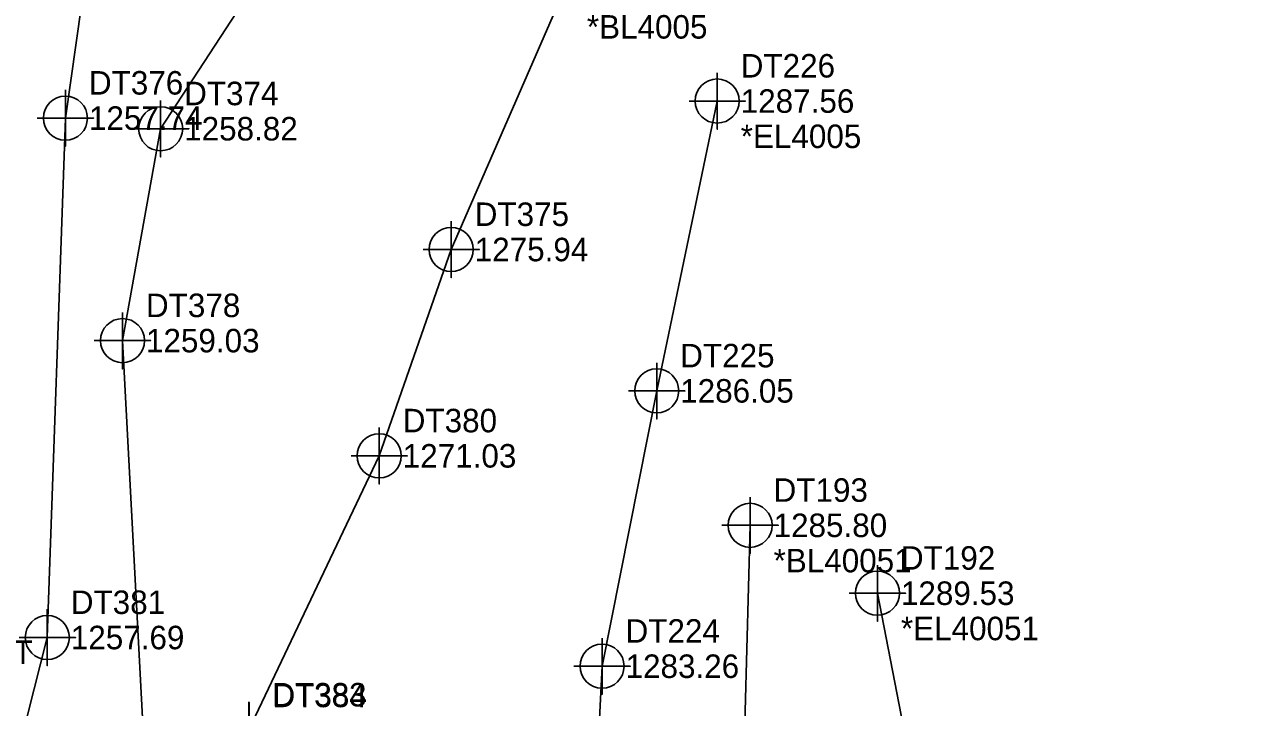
# Model space of a CAD drawing. Extents: x 1391270 to 1392151, y 960049 to 960667.
# Drawn here: x 1391612.7 to 1391741.8, y 960372.1 to 960444.8 of the extents above; entities that cross this region are included whole.
import ezdxf

# ---------------------------------------------------------------- set-up
doc = ezdxf.new("R2010")
doc.units = 0
for name, color, linetype in [('Exist DTM Breakline', 7, 'Continuous'), ('Exist DTM Breakline Cogo Comment', 7, 'Continuous'), ('Exist DTM Breakline Cogo Elevation', 7, 'Continuous'), ('Exist DTM Breakline Cogo Number', 7, 'Continuous'), ('Exist DTM Breakline Cogo Point CELL', 7, 'Continuous'), ('Exist DTM Breakline Underwater', 7, 'Continuous'), ('Exist DTM Breakline Underwater Cogo Elevation', 7, 'Continuous'), ('Exist DTM Breakline Underwater Cogo Number', 7, 'Continuous'), ('Exist DTM Breakline Underwater Cogo Point CELL', 7, 'Continuous'), ('Exist Hydro Stream or Body of Water', 7, 'Continuous'), ('Exist Hydro Stream or Body of Water Cogo Elevation', 7, 'Continuous'), ('Exist Hydro Stream or Body of Water Cogo Number', 7, 'Continuous'), ('Exist Hydro Stream or Body of Water Cogo Point CELL', 7, 'Continuous'), ('Exist Utilities Sanitary Sewer Manhole Cogo Comment', 7, 'Continuous')]:
    doc.layers.add(name, color=color, linetype=linetype)

msp = doc.modelspace()

# ---------------------------------------------------------------- linework, layer by layer
at = {"layer": 'Exist DTM Breakline'}
for p, q in [((1391670.034, 960448.283), (1391658.104, 960420.856)), ((1391658.104, 960420.856), (1391650.447, 960398.915)), ((1391650.447, 960398.915), (1391636.562, 960369.763))]:
    msp.add_line(p, q, dxfattribs=at)
for points in [[(1391677.683, 960326.497), (1391672.764, 960349.215), (1391674.149, 960376.543), (1391679.962, 960405.823), (1391686.399, 960436.645)], [(1391689.894, 960391.525), (1391689.18, 960365.157), (1391690.906, 960335.168), (1391693.62, 960320.244), (1391696.803, 960298.575), (1391694.311, 960295.44), (1391699.762, 960289.791)], [(1391945.147, 960195.757), (1391918.09, 960213.421), (1391881.206, 960222.292), (1391849.896, 960235.631), (1391826.517, 960251.571), (1391802.004, 960268.368), (1391783.721, 960280.05), (1391763.211, 960305.363), (1391726.912, 960330.123), (1391710.789, 960346.476), (1391703.438, 960384.306)]]:
    msp.add_lwpolyline(points, dxfattribs=at)
at = {"layer": 'Exist DTM Breakline Cogo Point CELL'}
for points in [[(1391686.399, 960439.645), (1391686.399, 960433.645), (1391686.399, 960436.645), (1391689.399, 960436.645), (1391683.399, 960436.645)], [(1391658.104, 960423.856), (1391658.104, 960417.856), (1391658.104, 960420.856), (1391661.104, 960420.856), (1391655.104, 960420.856)], [(1391679.962, 960408.823), (1391679.962, 960402.823), (1391679.962, 960405.823), (1391682.962, 960405.823), (1391676.962, 960405.823)], [(1391650.447, 960401.915), (1391650.447, 960395.915), (1391650.447, 960398.915), (1391653.447, 960398.915), (1391647.447, 960398.915)], [(1391689.894, 960394.525), (1391689.894, 960388.525), (1391689.894, 960391.525), (1391692.894, 960391.525), (1391686.894, 960391.525)], [(1391703.438, 960387.306), (1391703.438, 960381.306), (1391703.438, 960384.306), (1391706.438, 960384.306), (1391700.438, 960384.306)], [(1391674.149, 960379.543), (1391674.149, 960373.543), (1391674.149, 960376.543), (1391677.149, 960376.543), (1391671.149, 960376.543)], [(1391636.562, 960372.763), (1391636.562, 960366.763), (1391636.562, 960369.763), (1391639.562, 960369.763), (1391633.562, 960369.763)], [(1391636.599, 960372.686), (1391636.599, 960366.686), (1391636.599, 960369.686), (1391639.599, 960369.686), (1391633.599, 960369.686)]]:
    msp.add_lwpolyline(points, dxfattribs=at)
for centre in [(1391686.399, 960436.645), (1391658.104, 960420.856), (1391679.962, 960405.823), (1391650.447, 960398.915), (1391689.894, 960391.525), (1391703.438, 960384.306), (1391674.149, 960376.543)]:
    msp.add_circle(centre, 2.344, dxfattribs=at)
at = {"layer": 'Exist DTM Breakline Underwater'}
msp.add_lwpolyline([(1391637.721, 960501.208), (1391621.569, 960466.64), (1391617.066, 960434.832), (1391615.14, 960379.594), (1391599.785, 960319.127), (1391597.418, 960292.355)], dxfattribs=at)
at = {"layer": 'Exist DTM Breakline Underwater Cogo Point CELL'}
for points in [[(1391617.066, 960437.832), (1391617.066, 960431.832), (1391617.066, 960434.832), (1391620.066, 960434.832), (1391614.066, 960434.832)], [(1391615.14, 960382.594), (1391615.14, 960376.594), (1391615.14, 960379.594), (1391618.14, 960379.594), (1391612.14, 960379.594)]]:
    msp.add_lwpolyline(points, dxfattribs=at)
for centre in [(1391617.066, 960434.832), (1391615.14, 960379.594)]:
    msp.add_circle(centre, 2.344, dxfattribs=at)
at = {"layer": 'Exist Hydro Stream or Body of Water'}
msp.add_lwpolyline([(1391649.062, 960494.038), (1391648.634, 960466.546), (1391627.196, 960433.7), (1391623.135, 960411.167), (1391625.85, 960360.364), (1391618.453, 960319.772), (1391609.949, 960287.686), (1391599.63, 960231.778)], dxfattribs=at)
at = {"layer": 'Exist Hydro Stream or Body of Water Cogo Point CELL'}
for points in [[(1391624.196, 960433.7), (1391630.196, 960433.7), (1391627.196, 960433.7), (1391627.196, 960430.7), (1391627.196, 960436.7)], [(1391620.135, 960411.167), (1391626.135, 960411.167), (1391623.135, 960411.167), (1391623.135, 960408.167), (1391623.135, 960414.167)]]:
    msp.add_lwpolyline(points, dxfattribs=at)
for centre in [(1391627.196, 960433.7), (1391623.135, 960411.167)]:
    msp.add_circle(centre, 2.344, dxfattribs=at)

# ---------------------------------------------------------------- texts
at = {"layer": 'Exist DTM Breakline Cogo Comment'}
for s, p in [('*BL4005', (1391672.534, 960443.283)), ('*EL4005', (1391688.899, 960431.645)), ('*BL40051', (1391692.394, 960386.525)), ('*EL40051', (1391705.938, 960379.306))]:
    msp.add_text(s, height=2.5, dxfattribs=at).set_placement(p)
at = {"layer": 'Exist DTM Breakline Cogo Elevation'}
for s, p in [('1287.56', (1391688.899, 960435.395)), ('1275.94', (1391660.604, 960419.606)), ('1286.05', (1391682.462, 960404.573)), ('1271.03', (1391652.947, 960397.665)), ('1285.80', (1391692.394, 960390.275)), ('1289.53', (1391705.938, 960383.056)), ('1283.26', (1391676.649, 960375.293))]:
    msp.add_text(s, height=2.5, dxfattribs=at).set_placement(p)
at = {"layer": 'Exist DTM Breakline Cogo Number'}
for s, p in [('DT226', (1391688.899, 960439.145)), ('DT375', (1391660.604, 960423.356)), ('DT225', (1391682.462, 960408.323)), ('DT380', (1391652.947, 960401.415)), ('DT193', (1391692.394, 960394.025)), ('DT192', (1391705.938, 960386.806)), ('DT224', (1391676.649, 960379.043)), ('DT383', (1391639.062, 960372.263)), ('DT384', (1391639.099, 960372.186))]:
    msp.add_text(s, height=2.5, dxfattribs=at).set_placement(p)
at = {"layer": 'Exist DTM Breakline Underwater Cogo Elevation'}
for s, p in [('1257.74', (1391619.566, 960433.582)), ('1257.69', (1391617.64, 960378.344))]:
    msp.add_text(s, height=2.5, dxfattribs=at).set_placement(p)
at = {"layer": 'Exist DTM Breakline Underwater Cogo Number'}
for s, p in [('DT376', (1391619.566, 960437.332)), ('DT381', (1391617.64, 960382.094))]:
    msp.add_text(s, height=2.5, dxfattribs=at).set_placement(p)
at = {"layer": 'Exist Hydro Stream or Body of Water Cogo Elevation'}
for s, p in [('1258.82', (1391629.696, 960432.45)), ('1259.03', (1391625.635, 960409.917))]:
    msp.add_text(s, height=2.5, dxfattribs=at).set_placement(p)
at = {"layer": 'Exist Hydro Stream or Body of Water Cogo Number'}
for s, p in [('DT374', (1391629.696, 960436.2)), ('DT378', (1391625.635, 960413.667))]:
    msp.add_text(s, height=2.5, dxfattribs=at).set_placement(p)
at = {"layer": 'Exist Utilities Sanitary Sewer Manhole Cogo Comment'}
msp.add_text('3543 SEAT', height=2.5, dxfattribs=at).set_placement((1391596.478, 960376.783))

doc.saveas('drawing.dxf')
